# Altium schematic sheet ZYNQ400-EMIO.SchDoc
size A3
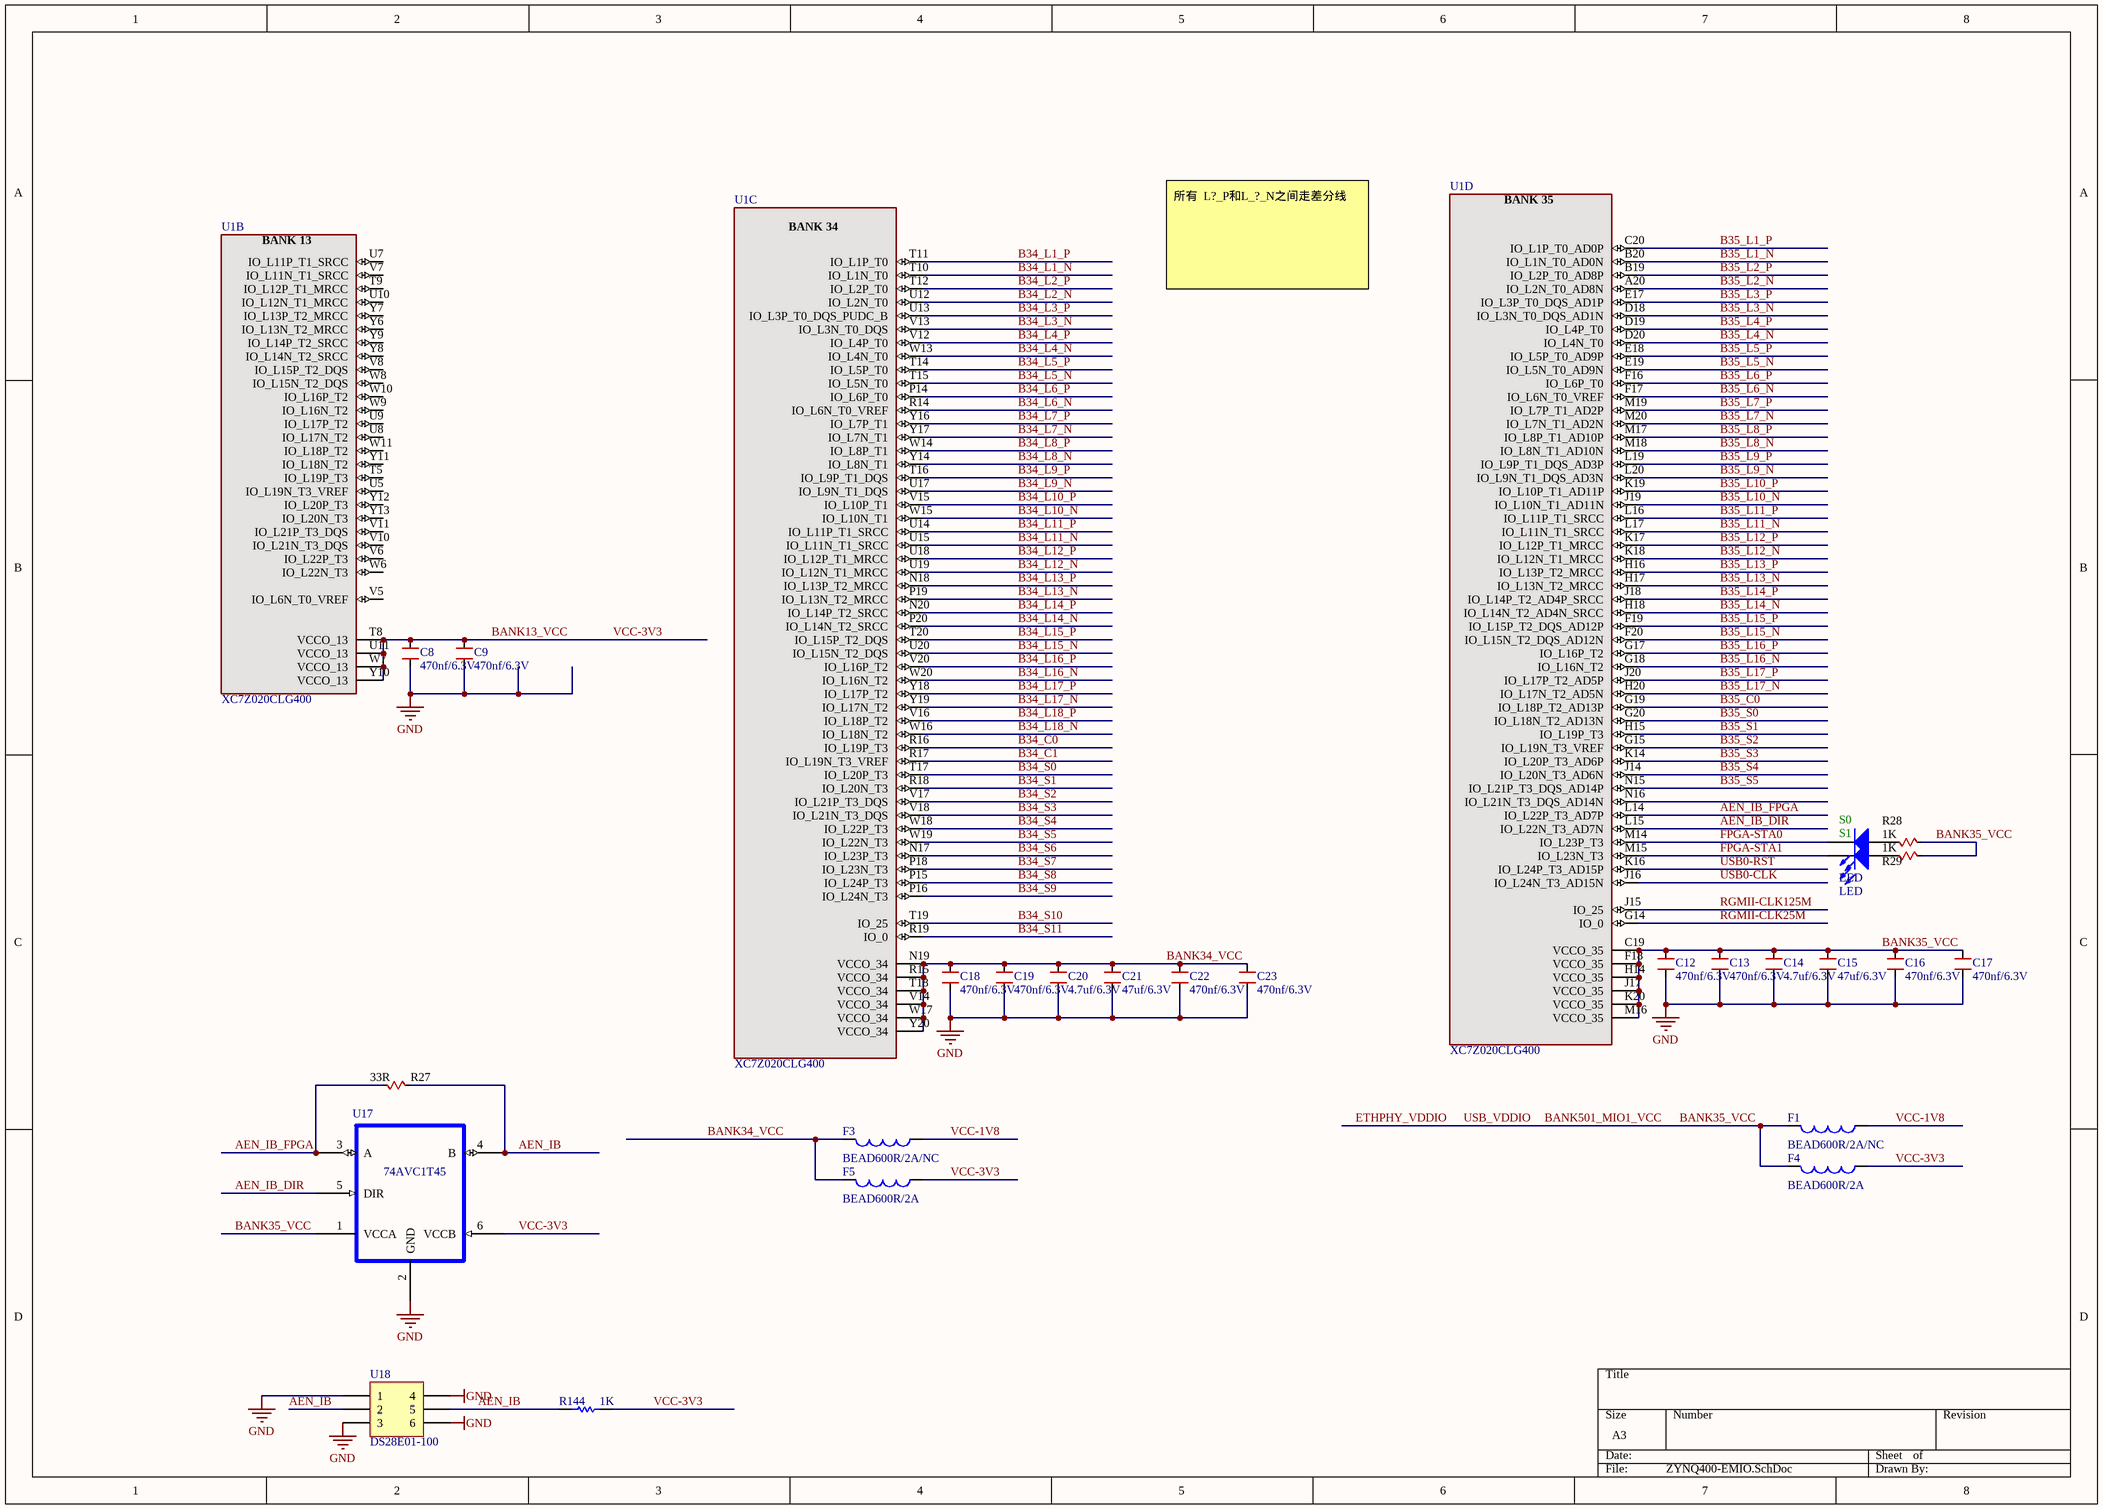
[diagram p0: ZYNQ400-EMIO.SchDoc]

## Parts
C8  470nf/6.3V  [0402]
C9  470nf/6.3V  [0402]
C12  470nf/6.3V  [0402]
C13  470nf/6.3V  [0402]
C14  4.7uf/6.3V  [0402]
C15  47uf/6.3V  [0402]
C16  470nf/6.3V  [0402]
C17  470nf/6.3V  [0402]
C18  470nf/6.3V  [0402]
C19  470nf/6.3V  [0402]
C20  4.7uf/6.3V  [0402]
C21  47uf/6.3V  [0402]
C22  470nf/6.3V  [0402]
C23  470nf/6.3V  [0402]
F1  BEAD600R/2A/NC  [0603]
F3  BEAD600R/2A/NC  [0603]
F4  BEAD600R/2A  [0603]
F5  BEAD600R/2A  [0603]
R27  value 33R  [0402]  (hidden comment: 0R/NC)
R28  1K  [0402]
R29  1K  [0402]
R144  1K  [0402]
S0  LED  [D0402]
S1  LED  [D0402]
U1  XC7Z020CLG400  [CLG400]  (parts B,C,D of 9)
U17  74AVC1T45  [SOT363]
U18  DS28E01-100  [TSOC]

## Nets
GND: C8.2 C9.2 C12.2 C13.2 C14.2 C15.2 C16.2 C17.2 C18.2 C19.2 C20.2 C21.2 C22.2 C23.2 U17.2(GND) U18.1 U18.3 U18.4 U18.6
AEN_IB: R27.2 R144.1 U17.4(B) U18.2 U18.5
AEN_IB_DIR: U1.L15(IO_L22N_T3_AD7N) U17.5(DIR)
AEN_IB_FPGA: R27.1 U1.L14(IO_L22P_T3_AD7P) U17.3(A)
B34_C0: U1.R16(IO_L19P_T3)
B34_C1: U1.R17(IO_L19N_T3_VREF)
B34_L1_N: U1.T10(IO_L1N_T0)
B34_L1_P: U1.T11(IO_L1P_T0)
B34_L2_N: U1.U12(IO_L2N_T0)
B34_L2_P: U1.T12(IO_L2P_T0)
B34_L3_N: U1.V13(IO_L3N_T0_DQS)
B34_L3_P: U1.U13(IO_L3P_T0_DQS_PUDC_B)
B34_L4_N: U1.W13(IO_L4N_T0)
B34_L4_P: U1.V12(IO_L4P_T0)
B34_L5_N: U1.T15(IO_L5N_T0)
B34_L5_P: U1.T14(IO_L5P_T0)
B34_L6_N: U1.R14(IO_L6N_T0_VREF)
B34_L6_P: U1.P14(IO_L6P_T0)
B34_L7_N: U1.Y17(IO_L7N_T1)
B34_L7_P: U1.Y16(IO_L7P_T1)
B34_L8_N: U1.Y14(IO_L8N_T1)
B34_L8_P: U1.W14(IO_L8P_T1)
B34_L9_N: U1.U17(IO_L9N_T1_DQS)
B34_L9_P: U1.T16(IO_L9P_T1_DQS)
B34_L10_N: U1.W15(IO_L10N_T1)
B34_L10_P: U1.V15(IO_L10P_T1)
B34_L11_N: U1.U15(IO_L11N_T1_SRCC)
B34_L11_P: U1.U14(IO_L11P_T1_SRCC)
B34_L12_N: U1.U19(IO_L12N_T1_MRCC)
B34_L12_P: U1.U18(IO_L12P_T1_MRCC)
B34_L13_N: U1.P19(IO_L13N_T2_MRCC)
B34_L13_P: U1.N18(IO_L13P_T2_MRCC)
B34_L14_N: U1.P20(IO_L14N_T2_SRCC)
B34_L14_P: U1.N20(IO_L14P_T2_SRCC)
B34_L15_N: U1.U20(IO_L15N_T2_DQS)
B34_L15_P: U1.T20(IO_L15P_T2_DQS)
B34_L16_N: U1.W20(IO_L16N_T2)
B34_L16_P: U1.V20(IO_L16P_T2)
B34_L17_N: U1.Y19(IO_L17N_T2)
B34_L17_P: U1.Y18(IO_L17P_T2)
B34_L18_N: U1.W16(IO_L18N_T2)
B34_L18_P: U1.V16(IO_L18P_T2)
B34_S0: U1.T17(IO_L20P_T3)
B34_S1: U1.R18(IO_L20N_T3)
B34_S2: U1.V17(IO_L21P_T3_DQS)
B34_S3: U1.V18(IO_L21N_T3_DQS)
B34_S4: U1.W18(IO_L22P_T3)
B34_S5: U1.W19(IO_L22N_T3)
B34_S6: U1.N17(IO_L23P_T3)
B34_S7: U1.P18(IO_L23N_T3)
B34_S8: U1.P15(IO_L24P_T3)
B34_S9: U1.P16(IO_L24N_T3)
B34_S10: U1.T19(IO_25)
B34_S11: U1.R19(IO_0)
B35_C0: U1.G19(IO_L18P_T2_AD13P)
B35_L1_N: U1.B20(IO_L1N_T0_AD0N)
B35_L1_P: U1.C20(IO_L1P_T0_AD0P)
B35_L2_N: U1.A20(IO_L2N_T0_AD8N)
B35_L2_P: U1.B19(IO_L2P_T0_AD8P)
B35_L3_N: U1.D18(IO_L3N_T0_DQS_AD1N)
B35_L3_P: U1.E17(IO_L3P_T0_DQS_AD1P)
B35_L4_N: U1.D20(IO_L4N_T0)
B35_L4_P: U1.D19(IO_L4P_T0)
B35_L5_N: U1.E19(IO_L5N_T0_AD9N)
B35_L5_P: U1.E18(IO_L5P_T0_AD9P)
B35_L6_N: U1.F17(IO_L6N_T0_VREF)
B35_L6_P: U1.F16(IO_L6P_T0)
B35_L7_N: U1.M20(IO_L7N_T1_AD2N)
B35_L7_P: U1.M19(IO_L7P_T1_AD2P)
B35_L8_N: U1.M18(IO_L8N_T1_AD10N)
B35_L8_P: U1.M17(IO_L8P_T1_AD10P)
B35_L9_N: U1.L20(IO_L9N_T1_DQS_AD3N)
B35_L9_P: U1.L19(IO_L9P_T1_DQS_AD3P)
B35_L10_N: U1.J19(IO_L10N_T1_AD11N)
B35_L10_P: U1.K19(IO_L10P_T1_AD11P)
B35_L11_N: U1.L17(IO_L11N_T1_SRCC)
B35_L11_P: U1.L16(IO_L11P_T1_SRCC)
B35_L12_N: U1.K18(IO_L12N_T1_MRCC)
B35_L12_P: U1.K17(IO_L12P_T1_MRCC)
B35_L13_N: U1.H17(IO_L13N_T2_MRCC)
B35_L13_P: U1.H16(IO_L13P_T2_MRCC)
B35_L14_N: U1.H18(IO_L14N_T2_AD4N_SRCC)
B35_L14_P: U1.J18(IO_L14P_T2_AD4P_SRCC)
B35_L15_N: U1.F20(IO_L15N_T2_DQS_AD12N)
B35_L15_P: U1.F19(IO_L15P_T2_DQS_AD12P)
B35_L16_N: U1.G18(IO_L16N_T2)
B35_L16_P: U1.G17(IO_L16P_T2)
B35_L17_N: U1.H20(IO_L17N_T2_AD5N)
B35_L17_P: U1.J20(IO_L17P_T2_AD5P)
B35_S0: U1.G20(IO_L18N_T2_AD13N)
B35_S1: U1.H15(IO_L19P_T3)
B35_S2: U1.G15(IO_L19N_T3_VREF)
B35_S3: U1.K14(IO_L20P_T3_AD6P)
B35_S4: U1.J14(IO_L20N_T3_AD6N)
B35_S5: U1.N15(IO_L21P_T3_DQS_AD14P)
BANK13_VCC: C8.1 C9.1 F4.1 F5.1 R144.2 U1.T8(VCCO_13) U1.U11(VCCO_13) U1.W7(VCCO_13) U1.Y10(VCCO_13) U17.6(VCCB)  [also labelled VCC-3V3]
BANK34_VCC: C18.1 C19.1 C20.1 C21.1 C22.1 C23.1 F3.2 F5.2 U1.N19(VCCO_34) U1.R15(VCCO_34) U1.T18(VCCO_34) U1.V14(VCCO_34) U1.W17(VCCO_34) U1.Y20(VCCO_34)
BANK35_VCC: C12.1 C13.1 C14.1 C15.1 C16.1 C17.1 F1.2 F4.2 R28.2 R29.2 U1.C19(VCCO_35) U1.F18(VCCO_35) U1.H14(VCCO_35) U1.J17(VCCO_35) U1.K20(VCCO_35) U1.M16(VCCO_35) U17.1(VCCA)  [also labelled BANK501_MIO1_VCC, ETHPHY_VDDIO, USB_VDDIO]
FPGA-STA0: S0.2(K) U1.M14(IO_L23P_T3)
FPGA-STA1: S1.2(K) U1.M15(IO_L23N_T3)
RGMII-CLK25M: U1.G14(IO_0)
RGMII-CLK125M: U1.J15(IO_25)
USB0-CLK: U1.J16(IO_L24N_T3_AD15N)
USB0-RST: U1.K16(IO_L24P_T3_AD15P)
VCC-1V8: F1.1 F3.1
NetR28_1: R28.1 S0.1(A)
NetR29_1: R29.1 S1.1(A)

Not connected (* = marked no-connect by the designer): U1 N16(IO_L21N_T3_DQS_AD14N) T5(IO_L19P_T3) T9(IO_L12P_T1_MRCC) U5(IO_L19N_T3_VREF) U7(IO_L11P_T1_SRCC) U8(IO_L17N_T2) U9(IO_L17P_T2) U10(IO_L12N_T1_MRCC) V5(IO_L6N_T0_VREF) V6(IO_L22P_T3) V7(IO_L11N_T1_SRCC) V8(IO_L15P_T2_DQS) V10(IO_L21N_T3_DQS) V11(IO_L21P_T3_DQS) W6(IO_L22N_T3) W8(IO_L15N_T2_DQS) W9(IO_L16N_T2) W10(IO_L16P_T2) W11(IO_L18P_T2) Y6(IO_L13N_T2_MRCC) Y7(IO_L13P_T2_MRCC) Y8(IO_L14N_T2_SRCC) Y9(IO_L14P_T2_SRCC) Y11(IO_L18N_T2) Y12(IO_L20P_T3) Y13(IO_L20N_T3)

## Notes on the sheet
- 所有  L?_P和L_?_N之间走差分线

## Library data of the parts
C8 C9 C12-C23 = CAPACITOR: Generic Capacitor
F1 F3-F5 = Inductor: Code_IEC: 1005
R27-R29 = RESISTOR: Generic Resistor
R144 = Res1: Resistor
S0 S1 = LED0: Typical INFRARED GaAs LED
U1 = XC7Z020-CLG400: Zynq 7000 FPGA 20 Die, in a CSG 484 Package; Manufacturer: Xilinx
U18 = Header 3X2A: Header, 3-Pin, Dual row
